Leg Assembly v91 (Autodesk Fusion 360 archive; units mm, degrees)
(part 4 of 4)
sketch "Sketch27" plane through (0, 0, 8.3168) normal (0, 0, 1) x axis (-1, 0, 0)
  line L1 (-1.5476, 25.3604) -> (3.2149, 20.5979)
  line L2 (-15.2451, 25.3604) -> (-1.5476, 25.3604)
  line L3 (-20.0076, 20.5979) -> (-15.2451, 25.3604)
  line L4 (-20.0076, 9.3042) -> (-20.0076, 20.5979)
  line L5 (-16.55, 9.3042) -> (-20.0076, 9.3042)
  line L6 (-20.0076, 2.9542) -> (-16.55, 2.9542)
  line L7 (-20.0076, -11.4458) -> (-20.0076, 2.9542)
  line L8 (-17.255, -11.4458) -> (-20.0076, -11.4458)
  line L9 (0.1537, -10.7673) -> (-3.4928, -7.1208)
  line L10 (0.1537, -18.4744) -> (0.1537, -10.7673)
  line L11 (-3.4928, -22.1208) -> (0.1537, -18.4744)
  line L12 (-20.0076, -17.7958) -> (-17.255, -17.7958)
  line L13 (-20.0076, -29.3396) -> (-20.0076, -17.7958)
  line L14 (-15.2451, -34.1021) -> (-20.0076, -29.3396)
  line L15 (-1.5476, -34.1021) -> (-15.2451, -34.1021)
  line L16 (3.2149, -29.3396) -> (-1.5476, -34.1021)
  line L17 (3.2149, 20.5979) -> (3.2149, -29.3396)
  line L18 (-16.55, 2.9542) -> (-16.55, 9.3042)
  line L19 (10.3682, 15.8479) -> (-27.1608, 15.8479)
  line L20 (10.3682, -3.5896) -> (10.3682, 15.8479)
  line L21 (-27.1608, -3.5896) -> (10.3682, -3.5896)
  line L22 (-27.1608, 15.8479) -> (-27.1608, -3.5896)
  line L23 (10.3682, -3.5896) -> (-27.1608, 15.8479)
  line L24 (-27.1608, -3.5896) -> (10.3682, 15.8479)
  line L25 (-22.7793, 18.2292) -> (-24.2215, 18.2292)
  line L26 (-8.8375, 18.2292) -> (-22.7793, 18.2292)
  arc A1 centre (-8.3963, 6.1292) radius 8.75 clockwise from (-16.55, 9.3042) to (-16.55, 2.9542)
  arc A2 centre (-9.026, -14.6208) radius 8.8203 clockwise from (-17.255, -11.4458) to (-13.668, -7.1208)
  arc A3 centre (-8.5804, -15.3408) radius 9.6671 clockwise from (-13.668, -7.1208) to (-3.4928, -7.1208)
  arc A4 centre (-8.5804, -13.9008) radius 9.6671 clockwise from (-3.4928, -22.1208) to (-13.668, -22.1208)
  arc A5 centre (-9.026, -14.6208) radius 8.8203 clockwise from (-13.668, -22.1208) to (-17.255, -17.7958)
  circle C1 centre (-13.2963, 20.4292) radius 2.2
  circle C2 centre (-13.2963, -29.1708) radius 2.2
  circle C3 centre (-3.4963, 20.4292) radius 2.2
  circle C4 centre (-3.4963, -29.1708) radius 2.2
  arc A6 centre (-8.3963, 6.1292) radius 8.75 clockwise from (-16.55, 9.3042) to (-16.55, 2.9542)
  circle C5 centre (-13.2963, 20.4292) radius 2.2
  point P39 (-8.3963, 6.1292)
  point P34 (-8.3963, 6.1292)
  horizontal L19
  perpendicular L19 L20
  parallel L19 L21
  parallel L20 L22
  coincident L23 P39
  coincident L24 P39
  coincident P34 P39
  perpendicular L4 L25
  perpendicular L4 L26
  tangent C1 L26
  dimension "d239" distance L19 L26 = 2.3813 (= "( 3 / 32 ) * 1 in")
extrude "Extrude12" cut sketch "Sketch27" profile of L4 L5 A1 L6 L7 L17 L18 L19 L21 L22 against normal blind 7.3152
extrude "Extrude13" add of existing geometry blind 2.7525
extrude "Extrude14" add of existing geometry blind 7.62
sketch "Sketch28" plane through (0, 0, 8.3168) normal (0, 0, 1) x axis (-1, 0, 0)
  line L1 (-13.1588, -1.2112) -> (-13.1588, -2.8708)
  line L2 (-20.0076, 2.9542) -> (-16.55, 2.9542)
  line L3 (-20.0076, -2.8708) -> (-20.0076, 2.9542)
  line L4 (-13.1588, -2.8708) -> (-20.0076, -2.8708)
  line L5 (-27.1608, -3.5896) -> (10.3682, -3.5896)
  line L6 (-27.1608, 15.8479) -> (-27.1608, -3.5896)
  line L7 (10.3682, -3.5896) -> (10.3682, 15.8479)
  line L8 (10.3682, 15.8479) -> (-27.1608, 15.8479)
  arc A1 centre (-8.3963, 6.1292) radius 8.75 clockwise from (-13.1588, -1.2112) to (-16.55, 2.9542)
extrude "Extrude3" cut sketch "Sketch28" against normal blind 7.3152
extrude "Extrude4" add of existing geometry blind 7.62
move "Move1"
move "Move1"
extrude "Extrude5" cut of existing geometry blind -0.3036 (= "-( 0.105700787401575 in - ( ( 3 / 32 ) * 1 in ) )")
extrude "Extrude6" add of existing geometry blind 3.175
extrude "Extrude7" add of existing geometry blind 3.175
position "Position10"
sketch "Sketch29" plane through (0, 0, -2.477) normal (0, 0, 1) x axis (-1, 0, 0)
  line L1 (-20.0076, -3.5896) -> (-20.0076, 15.8479)
  line L2 (3.2149, -3.5896) -> (-20.0076, -3.5896)
  line L3 (3.2149, 15.8479) -> (3.2149, -3.5896)
  line L4 (-20.0076, 15.8479) -> (3.2149, 15.8479)
  line L5 (0.8337, 15.8479) -> (3.2149, 15.8479)
  line L6 (0.8337, -3.5896) -> (0.8337, 15.8479)
  line L7 (3.2149, -3.5896) -> (0.8337, -3.5896)
  line L8 (3.2149, 15.8479) -> (3.2149, -3.5896)
  point P8 (0.8337, -3.5896)
  point P5 (3.2149, 15.8479)
  point P6 (3.2149, 15.8479)
  horizontal L5
  vertical L6
  horizontal L7
  vertical L8
  coincident L2 P8
  coincident P5 P6
  dimension "d256" distance L6 L8 = 2.3813 (= "( 3 / 32 ) * 1 in")
extrude "Extrude8" add sketch "Sketch29" profile of L2 L3 L4 L5 L6 L7 L8 along normal blind 10.795
extrude "Extrude9" cut of existing geometry blind -0.0012 (= "-4.921E-05 in")
extrude "Extrude10" cut of existing geometry blind -0.4572
extrude "Extrude11" cut of existing geometry blind -0.25
extrude "Extrude15" add of existing geometry blind 3.175
work_plane "WorkPlane6" AlongDistance -3.175
split "Split1"
remove_body "RemoveBody1"
remove_body "RemoveBody2"
extrude "Extrude12" new body of existing geometry blind 3.175
combine "Combine1"
extrude "Extrude16" add sketch "Sketch29" profile of L2 L3 L4 L5 L6 L7 L8 along normal blind 7.62
extrude "Extrude17" cut of existing geometry blind -0.0012 (= "-4.921E-05 in")
extrude "Extrude19" add of existing geometry blind 2
sketch "Sketch30" plane through (0, 0, 3.1168) normal (0, 0, 1) x axis (-1, 0, 0)
  line L1 (0.1537, -18.4744) -> (-3.4928, -22.1208)
  line L2 (0.1537, -10.7673) -> (0.1537, -18.4744)
  line L3 (-3.4928, -7.1208) -> (0.1537, -10.7673)
  line L4 (-20.0076, -11.4458) -> (-17.255, -11.4458)
  line L5 (-20.0076, -17.7958) -> (-20.0076, -11.4458)
  line L6 (-17.255, -17.7958) -> (-20.0076, -17.7958)
  line L7 (-20.0076, -17.7958) -> (-17.255, -17.7958)
  line L8 (-17.255, -11.4458) -> (-20.0076, -11.4458)
  line L9 (-12.5772, -11.4458) -> (-20.0076, -11.4458)
  line L10 (-12.5772, -17.7958) -> (-12.5772, -11.4458)
  line L11 (-20.0076, -17.7958) -> (-12.5772, -17.7958)
  line L12 (-20.0076, -11.4458) -> (-20.0076, -17.7958)
  line L13 (-3.4928, -22.1208) -> (-13.668, -22.1208)
  line L14 (-13.668, -7.1208) -> (-3.4928, -7.1208)
  arc A1 centre (-9.026, -14.6208) radius 8.8203 clockwise from (-13.668, -22.1208) to (-17.255, -17.7958)
  arc A2 centre (-9.026, -14.6208) radius 8.8203 clockwise from (-17.255, -11.4458) to (-13.668, -7.1208)
  point P15 (-20.0076, -11.4458)
  point P17 (-20.0076, -11.4458)
  point P13 (-17.255, -17.7958)
  horizontal L9
  vertical L10
  horizontal L11
  vertical L12
  coincident P15 P17
  coincident P13 L11
extrude "Extrude2" cut sketch "Sketch30" profile of L4 L5 L6 L7 L8 L9 L10 L11 L12 along normal blind 4.7625
extrude "Extrude20" cut of existing geometry blind -1.1906 (= "( -3 / 64 ) * 1 in")
sketch "Sketch31" plane through (0, 0, -2.1734) normal (0, 0, 1) x axis (-1, 0, 0)
  line L1 (-20.0076, 15.8479) -> (2.0243, 15.8479)
  line L2 (-20.0076, -3.5896) -> (-20.0076, 15.8479)
  line L3 (2.0243, -3.5896) -> (-20.0076, -3.5896)
  line L4 (2.0243, 15.8479) -> (2.0243, -3.5896)
  line L5 (-18.8169, -3.5896) -> (-20.0076, -3.5896)
  line L6 (-18.8169, 15.8479) -> (-18.8169, -3.5896)
  line L7 (-20.0076, 15.8479) -> (-18.8169, 15.8479)
  line L8 (-20.0076, -3.5896) -> (-20.0076, 15.8479)
  line L9 (-18.8169, 15.8479) -> (-20.0076, -3.5896)
  line L10 (-18.8169, -3.5896) -> (-20.0076, 15.8479)
  line L11 (-11.6624, 9.3042) -> (-27.1621, 9.3042)
  line L12 (-11.6624, 2.9542) -> (-11.6624, 9.3042)
  line L13 (-27.1621, 2.9542) -> (-11.6624, 2.9542)
  line L14 (-27.1621, 9.3042) -> (-27.1621, 2.9542)
  line L15 (-11.6624, 2.9542) -> (-27.1621, 9.3042)
  line L16 (-27.1621, 2.9542) -> (-11.6624, 9.3042)
  point P8 (-18.8169, 15.8479)
  point P4 (-20.0076, -3.5896)
  point P6 (-20.0076, -3.5896)
  point P10 (-20.0076, -3.5896)
  point P3 (-20.0076, 15.8479)
  point P11 (-20.0076, 15.8479)
  point P12 (-19.4122, 6.1292)
  point P17 (-19.4122, 6.1292)
  point P13 (-27.1621, 9.3042)
  point P16 (-27.1621, 2.9542)
  horizontal L5
  vertical L6
  horizontal L7
  vertical L8
  coincident L1 P8
  coincident P4 P6
  coincident P4 P10
  coincident P3 P11
  coincident L10 P12
  coincident L9 P12
  horizontal L11
  perpendicular L11 L12
  parallel L11 L13
  parallel L12 L14
  coincident L15 P17
  coincident L16 P17
  coincident P12 P17
  dimension "d282" distance L6 L8 = 1.1906 (= "( 3 / 64 ) * 1 in")
  dimension "d283" distance P13 P16 = 6.35
extrude "Extrude21" add sketch "Sketch31" profile of L1 L2 L3 L5 L6 L7 L8 L11 L13 along normal blind 7.3152
extrude "Extrude12" cut of existing geometry blind -1.1906 (= "( -3 / 64 ) * 1 in")
extrude "Extrude22" cut of existing geometry blind -0.3036 (= "( ( 3 / 32 ) * 1 in ) - 0.105700787401575 in")
extrude "Extrude13" add sketch "Sketch31" profile of L1 L2 L3 L5 L6 L7 L8 L11 L13 along normal blind 7.3152 and against normal blind 1.27
extrude "Extrude14" cut of existing geometry blind -0.7112
remove_instance "RemoveInstance3"
remove_instance "RemoveInstance1"
split "Split1"
split "Split2"
remove_body "RemoveBody1"
combine "Combine2"
offset_faces "OffsetFaces1" distance -0.5
move_face "MoveFace2"
move "Move1"
sketch "Sketch32" plane through (0, 0, 28) normal (0, 0, 1) x axis (-1, 0, 0)
  line L1 (-17.6263, 14.8742) -> (-17.6263, -23.6158)
  line L2 (0.8337, 14.8742) -> (-17.6263, 14.8742)
  line L3 (0.8337, -23.6158) -> (0.8337, 14.8742)
  line L4 (-17.6263, -23.6158) -> (0.8337, -23.6158)
  line L5 (-20.0076, -29.3396) -> (-20.0076, 20.5979)
  line L6 (-15.2451, -34.1021) -> (-20.0076, -29.3396)
  line L7 (-1.5476, -34.1021) -> (-15.2451, -34.1021)
  line L8 (3.2149, -29.3396) -> (-1.5476, -34.1021)
  line L9 (3.2149, 20.5979) -> (3.2149, -29.3396)
  line L10 (-1.5476, 25.3604) -> (3.2149, 20.5979)
  line L11 (-15.2451, 25.3604) -> (-1.5476, 25.3604)
  line L12 (-20.0076, 20.5979) -> (-15.2451, 25.3604)
  circle C1 centre (-13.2963, -29.1708) radius 1.7
  circle C2 centre (-3.4963, -29.1708) radius 1.7
  circle C3 centre (-3.4963, 20.4292) radius 1.7
  circle C4 centre (-13.2963, 20.4292) radius 1.7
  circle C5 centre (-30.0348, -20.1562) radius 4
  circle C6 centre (-30.0348, -20.1562) radius 7
  concentric C5 C6
  dimension "d298" diameter C5 = 8
  dimension "d299" diameter C6 = 14
extrude "Extrude13" new body sketch "Sketch32" profile of C5 C6 along normal blind 7
align "Align2"
split "Split1"
copy_paste_bodies "CutPasteBodies3"
sketch "Sketch34" plane through (0, 0, 26.3456) normal (0, 0, -1) x axis (1, 0, 0)
  circle C1 centre (8.3963, -14.6208) radius 3.175
extrude "Extrude1" cut sketch "Sketch34" against normal blind 8.95 (magnitude of "-15.3 mm + 6.35 mm")
extrude "Extrude6" cut of existing geometry blind -2.5908
extrude "Extrude1" add of existing geometry blind 0.9906
extrude "Extrude3" add of existing geometry blind 2.9769 (= "0.0234488188976379 in + ( ( 3 / 32 ) * 1 in )")
extrude "Extrude4" cut of existing geometry blind -2.9769 (= "-( 0.0234488188976379 in + ( ( 3 / 32 ) * 1 in ) )")
position "Position11"
move "Move1"
extrude "Extrude2" cut of existing geometry blind 2.2769 (= "0.0384586614173229 in + 1.3 mm")
align "Align1"
extrude "Extrude3" cut of existing geometry blind -2.286
extrude "Extrude4" add of existing geometry blind 1.0922
extrude "Extrude7" add of existing geometry blind 1.8796
align "Align3"
extrude "Extrude5" add of existing geometry blind 0.7937 (= "( 1 / 32 ) * 1 in")
extrude "Extrude6" cut of existing geometry blind -0.7937 (= "( -1 / 32 ) * 1 in")
move "Move2"
extrude "Extrude8" cut of existing geometry blind -0.7937 (= "( -1 / 32 ) * 1 in")
extrude "Extrude5" add of existing geometry blind 0.7937 (= "( 1 / 32 ) * 1 in")
align "Align2"
extrude "Extrude6" add of existing geometry blind 0.7937 (= "( 1 / 32 ) * 1 in")
extrude "Extrude7" add of existing geometry blind 2.0066
extrude "Extrude23" add of existing geometry blind 4.445 (= "0.30 in - 0.125 in")
extrude "Extrude2" cut of existing geometry blind -4.1402
component_from_bodies "Body->Comp3"
copy_paste "CutPaste8"
sketch "Sketch35" plane through (-3.2149, 0, 0) normal (-1, 0, 0) x axis (0, -1, 0)
  line L1 (-11.4458, 5.1418) -> (-11.4458, 7.8793)
  line L2 (20.5979, 5.1418) -> (-11.4458, 5.1418)
  line L3 (20.5979, 28) -> (20.5979, 5.1418)
  line L4 (-29.3396, 28) -> (20.5979, 28)
  line L5 (-29.3396, 5.1418) -> (-29.3396, 28)
  line L6 (-17.7958, 5.1418) -> (-29.3396, 5.1418)
  line L7 (-17.7958, 7.8793) -> (-17.7958, 5.1418)
  line L8 (-11.4458, 7.8793) -> (-17.7958, 7.8793)
  line L9 (-7.6208, 17.8125) -> (-21.6208, 17.8125)
  line L10 (-7.6208, 24.8125) -> (-21.6208, 24.8125)
  line L11 (-21.6208, 17.8125) -> (-7.6208, 24.8125)
  line L12 (-21.6208, 24.8125) -> (-7.6208, 17.8125)
  circle C1 centre (-14.6208, 21.3125) radius 3.5
  point P13 (-7.6208, 24.8125)
  point P14 (-7.6208, 24.8125)
  point P10 (-21.6208, 17.8125)
  point P15 (-21.6208, 17.8125)
  point P11 (-7.6208, 17.8125)
  point P16 (-7.6208, 17.8125)
  point P12 (-21.6208, 24.8125)
  point P17 (-21.6208, 24.8125)
  point P18 (-14.6208, 21.3125)
  coincident P13 P14
  coincident P10 P15
  coincident P11 P16
  coincident P12 P17
  midpoint L11 P18
  dimension "d336" diameter C1 = 7
sketch "Sketch37" plane through (0, 0, 17.8125) normal (0, 0, 1) x axis (-1, 0, 0)
  line L1 (0.0837, 3.7223) -> (0.0837, -22.8658)
  line L2 (-16.8763, -22.8658) -> (-16.8763, 3.7223)
  line L3 (0.0837, -22.8658) -> (-16.8763, -22.8658)
  circle C1 centre (-8.3963, -14.6208) radius 8
  arc A1 centre (-8.3963, 5.8792) radius 8.75 clockwise from (0.0837, 3.7223) to (-16.8763, 3.7223)
  circle C2 centre (-8.3963, -14.6208) radius 8
  circle C3 centre (-8.3963, -14.6208) radius 7
  circle C4 centre (-8.3963, -14.6208) radius 7
  circle C5 centre (-8.3963, -14.6208) radius 7.2
  dimension "d345" = 0.2
extrude "Extrude14" new body sketch "Sketch37" profile of C1 L1 A1 L2 L3 C2 C5 along normal blind 8.5875
combine "Combine3"
extrude "Extrude11" cut sketch "Sketch35" profile of C1 against normal blind 35.56
sketch "Sketch38" plane through (-0.8337, 0, 0) normal (1, 0, 0) x axis (0, 1, 0)
  line L1 (-14.8742, 28) -> (23.6158, 28)
  line L2 (-14.8742, 26.4) -> (-14.8742, 28)
  line L3 (23.6158, 26.4) -> (-14.8742, 26.4)
  line L4 (23.6158, 28) -> (23.6158, 26.4)
  line L5 (18.1208, 17.8125) -> (11.1208, 17.8125)
  line L6 (18.1208, 24.8125) -> (18.1208, 17.8125)
  line L7 (11.1208, 24.8125) -> (18.1208, 24.8125)
  line L8 (11.1208, 17.8125) -> (11.1208, 24.8125)
  line L9 (18.1208, 24.8125) -> (11.1208, 17.8125)
  line L10 (11.1208, 24.8125) -> (18.1208, 17.8125)
  line L11 (22.6208, 17.8125) -> (14.6208, 17.8125)
  line L12 (21.8208, 17.8125) -> (14.6208, 17.8125)
  line L13 (18.1208, 24.8125) -> (11.1208, 24.8125)
  line L14 (18.1208, 30.6305) -> (18.1208, 24.8125)
  line L15 (11.1208, 30.6305) -> (18.1208, 30.6305)
  line L16 (11.1208, 24.8125) -> (11.1208, 30.6305)
  circle C1 centre (14.6208, 21.3125) radius 3.5
  point P11 (14.6208, 21.3125)
  point P6 (14.6208, 21.3125)
  point P14 (21.8208, 17.8125)
  point P9 (18.1208, 24.8125)
  point P7 (11.1208, 17.8125)
  point P8 (18.1208, 17.8125)
  horizontal L5
  perpendicular L5 L6
  parallel L5 L7
  parallel L6 L8
  coincident L9 P11
  coincident L10 P11
  coincident P6 P11
  coincident L5 P14
  horizontal L13
  vertical L14
  horizontal L15
  vertical L16
  coincident P9 L14
  dimension "d358" distance P7 P8 = 7
extrude "Extrude12" cut sketch "Sketch38" profile of L1 L3 C1 L5 L6 L7 L8 L11 L12 L13 L14 L15 L16 along normal blind 18.46
extrude "Extrude8" add of existing geometry blind 0.5 (= "0.5 * ( 0.1018700787401575 in - ( ( 1 / 16 ) * 1 in ) )")
extrude "Extrude9" add of existing geometry blind 0.5 (= "0.5 * ( 0.1018700787401575 in - ( ( 1 / 16 ) * 1 in ) )")
work_plane "WorkPlane8" RotateAngle 0
sketch "Sketch39" plane through (4.3963, 14.6208, 18.5259) normal (-1, 0, 0) x axis (0, 1, 0)
  circle C1 centre (0, -2.7866) radius 3.5
  circle C2 centre (0, -2.7866) radius 2
  concentric C1 C2
  dimension "d366" diameter C2 = 4
extrude "Extrude10" cut sketch "Sketch39" profile of C2 against normal blind 1.5
extrude "Extrude9" add of existing geometry blind 0.125 (= "0.25 mm / 2")
extrude "Extrude10" add of existing geometry blind 0.125 (= "0.25 mm / 2")
extrude "Extrude11" add of existing geometry blind 2.032
sketch "Sketch40" plane through (0, 0, 24.8191) normal (0, 0, 1) x axis (-1, 0, 0)
  line L1 (-7.6026, -12.7708) -> (-7.6026, -16.4708)
  line L2 (-9.1901, -12.7708) -> (-7.6026, -12.7708)
  line L3 (-9.1901, -16.4708) -> (-9.1901, -12.7708)
  line L4 (-7.6026, -16.4708) -> (-9.1901, -16.4708)
  line L5 (-7.3526, -12.5208) -> (-7.3526, -16.7208)
  line L6 (-9.4401, -12.5208) -> (-7.3526, -12.5208)
  line L7 (-9.4401, -16.7208) -> (-9.4401, -12.5208)
  line L8 (-7.3526, -16.7208) -> (-9.4401, -16.7208)
  circle C1 centre (-8.3963, -14.6208) radius 4
  dimension "d375" = 0.25
extrude "Extrude12" cut sketch "Sketch40" profile of L1 L2 L3 L4 L5 L6 L7 L8 against normal blind 12.0142
delete_face "DeleteFace8"
delete_face "DeleteFace9"
delete_face "DeleteFace5"
delete_face "DeleteFace6"
delete_face "DeleteFace10"
delete_face "DeleteFace7"
delete_face "DeleteFace11"
delete_face "DeleteFace8"
fillet "Fillet2" radius 3.175
sketch "Sketch41" plane through (0, 0, 1.968) normal (0, 0, 1) x axis (-1, 0, 0)
  line L1 (-20.0076, 9.0542) -> (-18.8169, 9.0542)
  line L2 (-20.0076, 2.7042) -> (-20.0076, 9.0542)
  line L3 (-18.8169, 2.7042) -> (-20.0076, 2.7042)
  line L4 (-18.8169, -3.8396) -> (-18.8169, 2.7042)
  line L5 (2.0243, -3.8396) -> (-18.8169, -3.8396)
  line L6 (2.0243, 15.5979) -> (2.0243, -3.8396)
  line L7 (-18.8169, 15.5979) -> (2.0243, 15.5979)
  line L8 (-18.8169, 9.0542) -> (-18.8169, 15.5979)
  line L9 (-12.9401, 2.7042) -> (-20.0076, 2.7042)
  line L10 (-12.9401, 9.0542) -> (-12.9401, 2.7042)
  line L11 (-20.0076, 9.0542) -> (-12.9401, 9.0542)
  line L12 (-20.0076, 2.7042) -> (-20.0076, 9.0542)
  circle C1 centre (-8.3963, 5.8792) radius 8.75
  circle C2 centre (-8.3963, 5.8792) radius 8.75
  point P4 (-20.0076, 2.7042)
  point P11 (-20.0076, 2.7042)
  point P3 (-20.0076, 9.0542)
  point P14 (-20.0076, 9.0542)
  horizontal L9
  vertical L10
  horizontal L11
  vertical L12
  coincident P4 P11
  coincident P3 P14
extrude "Extrude24" add sketch "Sketch41" profile of L4 L5 L6 L7 L8 C1 C2 L9 L11 along normal blind 3.1738
extrude "Extrude13" cut of existing geometry blind -1
extrude "Extrude13" add of existing geometry blind 2.7375
as_built_joint "As-built2"
remove_instance "RemoveInstance3"
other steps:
base_feature "Base Feature1"
base_feature "Base Feature1"
base_feature "Base Feature1"
base_feature "Base Feature1"
base_feature "Base Feature1"
base_feature "Base Feature1"
base_feature "Base Feature1"
base_feature "Base Feature1"
base_feature "Base Feature1"
base_feature "Base Feature2"
move "Move1"
base_feature "Base Feature1"
base_feature "Base Feature3"
move "Move2"
base_feature "Base Feature2"
base_feature "Base Feature2"
move "Move1"
base_feature "Base Feature4"
base_feature "Base Feature3"
move "Move2"
base_feature "Base Feature1"
delete_face "DeleteFace5"
delete_face "DeleteFace6"
delete_face "DeleteFace7"
offset_faces "OffsetFaces1" distance -3.175
chamfer "Chamfer1" distance 4.7625
move_face "MoveFace1"
base_feature "Base Feature1"
fillet "Fillet1" radius 3.175
create_component "CreateComponent1"
create_component "CreateComponent2"
create_component "CreateComponent1"
create_component "CreateComponent1"
create_component "CreateComponent2"
create_component "CreateComponent2"
remove_body "RemoveBody1"
remove_body "RemoveBody1"
remove_body "RemoveBody2"
create_component "CreateComponent3"
remove_body "RemoveBody1"
create_component "CreateComponent3"
remove_body "RemoveBody3"
remove_instance "RemoveInstance1"
create_component "CreateComponent4"
remove_instance "RemoveInstance2"
remove_body "RemoveBody1"
remove_body "RemoveBody4"
create_component "CreateComponent1"
remove_body "RemoveBody2"
remove_body "RemoveBody3"
remove_body "RemoveBody4"
remove_body "RemoveBody6"
remove_instance "RemoveInstance1"
remove_body "RemoveBody7"
remove_body "RemoveBody9"
remove_instance "RemoveInstance1"
remove_body "RemoveBody5"
remove_body "RemoveBody6"
remove_body "RemoveBody1"
remove_body "RemoveBody2"
create_component "CreateComponent5"
remove_instance "RemoveInstance3"
create_component "CreateComponent1"
create_component "CreateComponent2"
create_component "CreateComponent3"
create_component "CreateComponent4"
create_component "CreateComponent5"
create_component "CreateComponent6"
create_component "CreateComponent6"
remove_instance "RemoveInstance1"
create_component "CreateComponent1"
remove_body "RemoveBody5"
create_component "CreateComponent2"
remove_body "RemoveBody6"
create_component "CreateComponent3"
remove_body "RemoveBody7"
create_component "CreateComponent7"
remove_instance "RemoveInstance5"
remove_instance "RemoveInstance2"
create_component "CreateComponent26"
remove_instance "RemoveInstance9"
create_component "CreateComponent27"
remove_body "RemoveBody10"
remove_instance "RemoveInstance10"
create_component "CreateComponent28"
remove_instance "RemoveInstance11"
remove_instance "RemoveInstance12"
remove_body "RemoveBody11"
remove_body "RemoveBody1"
create_component "CreateComponent48"
remove_body "RemoveBody13"
remove_instance "RemoveInstance13"
remove_body "RemoveBody14"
